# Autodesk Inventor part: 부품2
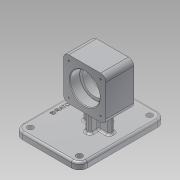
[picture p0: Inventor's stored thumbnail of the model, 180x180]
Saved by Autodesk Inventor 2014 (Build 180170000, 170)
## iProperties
Created: 2020-11
Part Number: 부품2
Material: 알루미늄 6061
Document SubType Name: Modeling
Designer: NET
Density: 2.71 g/cm^3
Appearance: 알루미늄 - 평지
Mass: 683.566 g
Surface Area: 546.675 cm^2
Volume: 252.238 cm^3
Author: NET
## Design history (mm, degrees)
sketch "스케치1"
  geometry: L1 (0, 0)-(64, 0); L2 (64, 0)-(64, 64); L3 (64, 64)-(0, 64); L4 (0, 64)-(0, 0)
  constraints: 8 end point, 2 parallel, 1 horizontal, 1 perpendicular
  dimensions: "d0" = 64 distance of L2.end L3.end; "d1" = 64 distance of L1.end L2.end
extrude "돌출1" new body sketch "스케치1" distance "d2" = 42; taper "d3" = 0 deg
sketch "스케치2"
  geometry: L1 (0, 0)-(0, 64) reference; L2 (0, 64)-(-64, 64) reference; L3 (-64, 64)-(-64, 0) reference; L4 (-64, 0)-(0, 0) reference; L5 (-32, 64)-(-32, 0); L6 (-64, 32)-(0, 32); C1 r 18 at (-32, 32)
  constraints: 5 midpoint, 4 end point, 1 centre point
  dimensions: "d4" = 36 diameter of C1
extrude "돌출2" cut sketch "스케치2" stored distance "d5" = 42; taper "d6" = 0 deg
sketch "스케치3"
  geometry: C1 r 18 at (-32, 32) reference; C2 r 22.5 at (-32, 32)
  constraints: 1 centre point, 1 coincident
  dimensions: "d7" = 45 diameter of C2
extrude "돌출3" cut sketch "스케치3" distance "d8" = 15; taper "d9" = 0 deg
sketch "스케치4"
  geometry: C1 r 18 at (32, 32) reference; C2 r 21 at (32, 32)
  constraints: 1 centre point, 1 coincident
  dimensions: "d10" = 42 diameter of C2
extrude "돌출4" cut sketch "스케치4" distance "d11" = 15; taper "d12" = 0 deg
node "작업 평면1"
sketch "스케치5"
  geometry: L1 (0, 0)-(0, 64) reference; L2 (0, 64)-(-42, 64) reference; L3 (-42, 0)-(-42, 64) reference; L4 (0, 0)-(-42, 0) reference; L5 (-21, 64)-(-21, 0); L6 (0, 32)-(-42, 32); L7 (44, -30)-(-86, -30); L8 (-86, -30)-(-86, 68); L9 (-86, 68)-(44, 68); L10 (44, 68)-(44, -30); L11 (44, -30)-(-86, 68); L12 (-86, -30)-(44, 68); 2 further points
  constraints: 16 end point, 6 midpoint, 2 parallel, 1 horizontal, 1 perpendicular, 1 point on line
  dimensions: "d14" = 130 distance of L8.end L9.end; "d15" = 98 distance of L7.end L8.end; "d16" = 62 vertical distance of L7.end L6.end
extrude "돌출5" join sketch "스케치5" distance "d17" = 10; taper "d18" = 0 deg
fillet "모깎기1" dims "d19" = 12
sketch "스케치6"
  geometry: C1 r 4.5 at (-74, 56); C2 r 4.5 at (-74, -18); C3 r 4.5 at (32, -18); C4 r 4.5 at (32, 56); A1 r 12 centre (32, -18) between (32, -30) and (44, -18) reference; A2 r 12 centre (32, 56) between (44, 56) and (32, 68) reference; A3 r 12 centre (-74, 56) between (-74, 68) and (-86, 56) reference; A4 r 12 centre (-74, -18) between (-86, -18) and (-74, -30) reference; 1 further point
  constraints: 4 centre point, 4 coincident
  dimensions: "d20" = 9 diameter of C1; "d21" = 9 diameter of C2; "d22" = 9 diameter of C3; "d23" = 9 diameter of C4
extrude "돌출6" cut sketch "스케치6" stored distance "d24" = 10; taper "d25" = 0 deg
sketch "스케치7"
  geometry: L1 (-56, 8)-(-8, 8); L2 (-8, 8)-(-8, 56); L3 (-8, 56)-(-56, 56); L4 (-56, 56)-(-56, 8); L5 (-56, 8)-(-8, 56); L6 (-8, 8)-(-56, 56); C1 r 22.5 at (-32, 32) reference; 6 further points
  constraints: 12 end point, 5 coincident, 3 midpoint, 2 parallel, 1 horizontal, 1 perpendicular
  dimensions: "d26" = 48 distance of L1.start L1.end; "d27" = 48 distance of L3.end L1.start
hole "구멍1" sketch "스케치7" at (-56, 56), (-8, 56), (-8, 8), (-56, 8) diameter "d28" = 2.459; stored, may be unused: countersink angle "d32" = 90 deg, drill point angle "d34" = 118 deg; dims "d29" = 8, "d30" = 4, "d31" = 2, "d33" = 10
sketch "스케치8"
  geometry: L1 (8, 8)-(56, 8); L2 (56, 8)-(56, 56); L3 (56, 56)-(8, 56); L4 (8, 56)-(8, 8); L5 (8, 8)-(56, 56); L6 (56, 8)-(8, 56); C1 r 21 at (32, 32) reference; 4 further points
  constraints: 12 end point, 4 coincident, 2 midpoint, 2 parallel, 1 horizontal, 1 perpendicular
  dimensions: "d35" = 48 distance of L3.end L1.start; "d36" = 48 distance of L2.end L3.end
hole "구멍2" sketch "스케치8" at (8, 56), (56, 56), (56, 8), (8, 8) diameter "d37" = 2.459; stored, may be unused: countersink angle "d41" = 90 deg, drill point angle "d43" = 118 deg; dims "d38" = 8, "d39" = 4, "d40" = 2, "d42" = 10
fillet "모깎기2" dims "d44" = 8
fillet "모깎기3" dims "d45" = 3
sketch "스케치9"
  geometry: L1 (83, 56)-(83, -18) reference; L2 (-32, 65)-(74, 65) reference; L3 (-41, -18)-(-41, 56) reference; L4 (74, -27)-(-32, -27) reference; L5 (21, -27)-(21, 65); L6 (-41, 32)-(83, 32); L7 (-32, -30)-(74, -30) reference; L8 (38, 28)-(4, 28); L9 (4, 28)-(4, 36); L10 (4, 36)-(38, 36); L11 (38, 36)-(38, 28); L12 (38, 28)-(4, 36); L13 (4, 28)-(38, 36); L14 (25, 52)-(17, 52); L15 (17, 52)-(17, 12); L16 (17, 12)-(25, 12); L17 (25, 12)-(25, 52); L18 (25, 52)-(17, 12); L19 (17, 52)-(25, 12); 3 further points
  constraints: 28 end point, 8 midpoint, 4 parallel, 3 perpendicular, 2 horizontal, 2 point on line
  dimensions: "d46" = 62 distance between parallel lines of L7 L6; "d47" = 8 distance of L15.end L16.end; "d48" = 8 distance of L8.end L9.end; "d49" = 34 distance of L9.end L10.end; "d50" = 40 distance of L14.end L15.end
extrude "돌출7" join sketch "스케치9" stored distance "d51" = 10; taper "d52" = 0 deg
fillet "모깎기4" dims "d53" = 3
fillet "모깎기5" dims "d54" = 3
fillet "모깎기6" dims "d55" = 0.3
chamfer "모따기1" distance "d56" = 1; stored, may be unused: second distance "d57" = 2, angle "d58" = 45 deg
sketch "스케치10"
  geometry: L1 (-32, 65)-(74, 65) reference; L2 (74, -27)-(-32, -27) reference; L3 (21, -27)-(21, 65); L4 (-44, 56)-(-44, -18) reference; L5 (-32, -30)-(74, -30) reference; 2 further points
  constraints: 2 end point, 2 midpoint, 1 other
  dimensions: "d59" = 65 distance from line of L4 point (21, -20); "d60" = 10 distance from line of L5 point (21, -20)
extrude "돌출8" join sketch "스케치10" distance "d61" = 0.5; taper "d62" = 0 deg
node "솔리드1"
node "투영된 루프1"
other parameters: "d13" = -38
